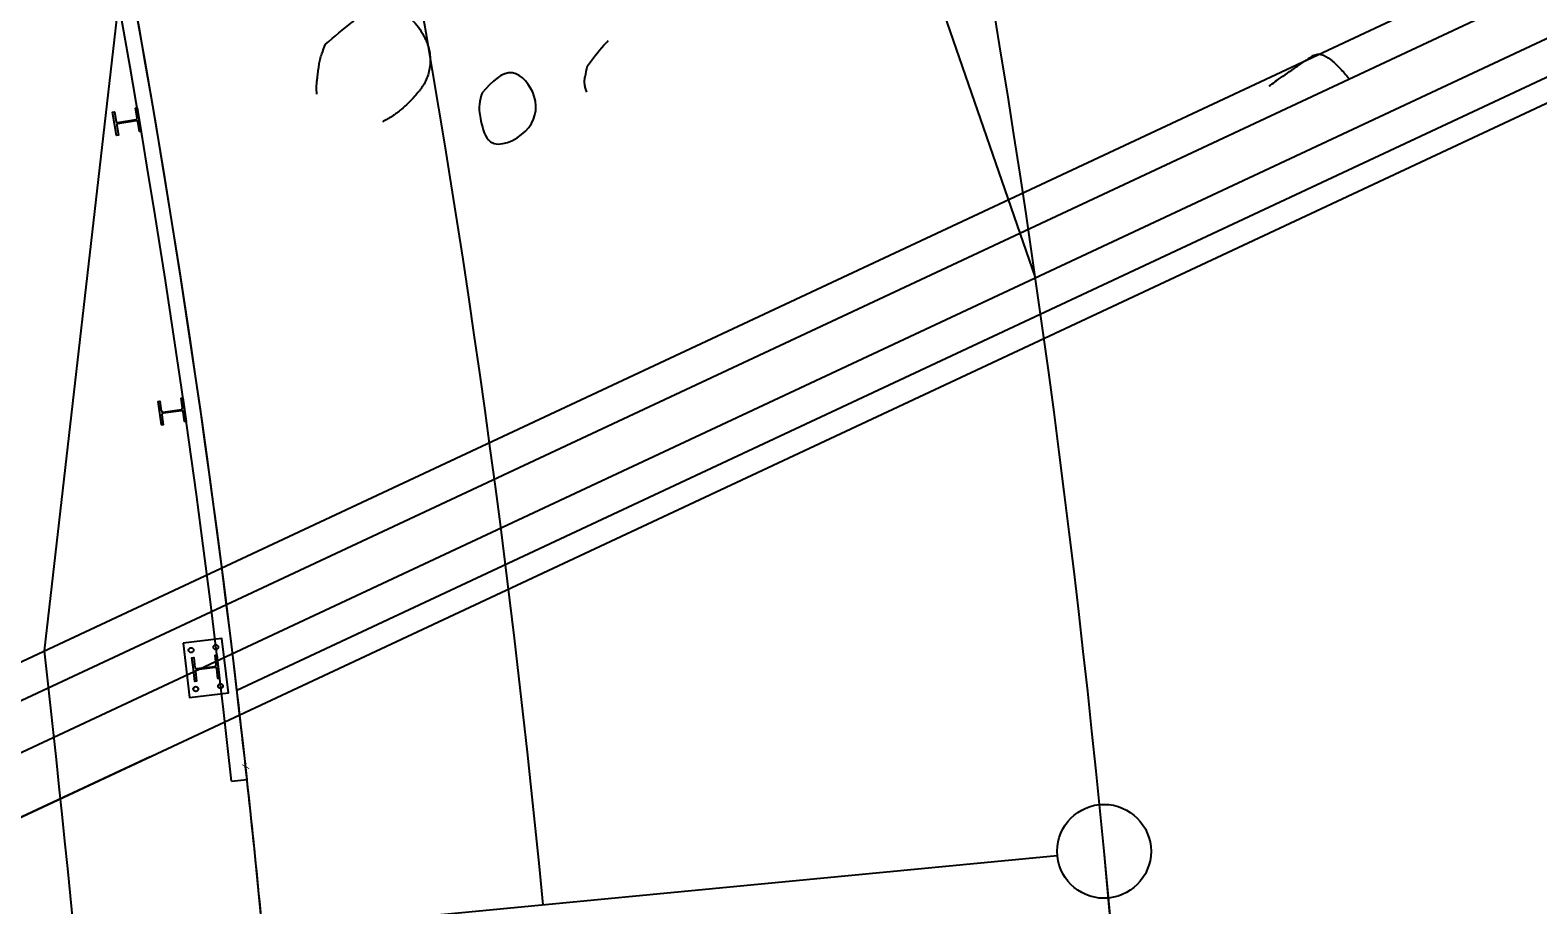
# Model space of a CAD drawing. Extents: x 2355002 to 2355569, y 708374 to 709566.
# Drawn here: x 2355338.73 to 2355370.84, y 709251.3 to 709269.92 of the extents above; entities that cross this region are included whole.
import ezdxf

# ---------------------------------------------------------------- set-up
doc = ezdxf.new("R2010")
doc.units = 0
for name, color, linetype in [('BD_X_Building', 7, 'Continuous'), ('BR_X_Brg_Centerline', 7, 'Continuous'), ('BR_X_Det_Centerline', 7, 'Continuous'), ('BR_X_Gen_Approach_Slab', 7, 'Continuous'), ('BR_X_Rail_Stl_Det', 7, 'Continuous'), ('BR_X_Slab_Object', 7, 'Continuous'), ('DR_X_Cells', 7, 'Continuous'), ('DT_X_Slope_Break_Line', 7, 'Continuous'), ('GK_Drainage_Nodes', 7, 'Continuous'), ('PM_X_CL_Double_Solid', 7, 'Continuous'), ('PM_X_Edge_Line', 7, 'Continuous'), ('PM_X_Stop_Line', 7, 'Continuous'), ('RD_X_GR_Rt', 7, 'Continuous'), ('RD_X_Wall', 7, 'Continuous'), ('SH_Text', 7, 'Continuous'), ('UT_X_Water_Cells', 7, 'Continuous'), ('VG_X_Cells', 7, 'Continuous'), ('VG_X_Tree_Line_Rt', 7, 'Continuous')]:
    doc.layers.add(name, color=color, linetype=linetype)

msp = doc.modelspace()

# ---------------------------------------------------------------- linework, layer by layer
at = {"layer": 'BD_X_Building'}
msp.add_arc((2355104.75, 709227.886), 272.024, 5.4603, 29.69206, dxfattribs=at)
at = {"layer": 'BR_X_Brg_Centerline'}
msp.add_line((2355335.913, 709253.31), (2355387.539, 709277.472), dxfattribs=at)
at = {"layer": 'BR_X_Det_Centerline'}
msp.add_line((2355360.141, 709264.65), (2355328.268, 709356.793), dxfattribs=at)
at = {"layer": 'BR_X_Gen_Approach_Slab'}
msp.add_line((2355343.137, 709255.863), (2355377.253, 709271.831), dxfattribs=at)
at = {"layer": 'BR_X_Rail_Stl_Det'}
msp.add_line((2355343.022, 709253.925), (2355343.353, 709253.961), dxfattribs=at)
for points in [[(2355340.533, 709267.925), (2355340.491, 709268.174), (2355340.528, 709268.181), (2355340.563, 709267.974)], [(2355340.598, 709267.949), (2355340.988, 709268.015)], [(2355340.993, 709267.989), (2355340.602, 709267.923)], [(2355341.013, 709268.05), (2355340.978, 709268.257), (2355341.015, 709268.263), (2355341.1, 709267.764), (2355341.062, 709267.758), (2355341.027, 709267.965)], [(2355340.578, 709267.888), (2355340.613, 709267.681), (2355340.576, 709267.675), (2355340.533, 709267.925)], [(2355341.497, 709261.764), (2355341.461, 709262.014), (2355341.499, 709262.02), (2355341.528, 709261.812)], [(2355341.98, 709261.876), (2355341.95, 709262.084), (2355341.987, 709262.09), (2355342.059, 709261.588), (2355342.022, 709261.583), (2355341.992, 709261.791)], [(2355341.541, 709261.726), (2355341.57, 709261.518), (2355341.533, 709261.513), (2355341.497, 709261.764)], [(2355341.562, 709261.786), (2355341.954, 709261.843)], [(2355341.958, 709261.816), (2355341.566, 709261.76)], [(2355341.992, 709256.865), (2355342.131, 709255.707), (2355342.958, 709255.806), (2355342.819, 709256.964), (2355341.992, 709256.865)], [(2355342.211, 709256.304), (2355342.181, 709256.555), (2355342.219, 709256.56), (2355342.244, 709256.351)], [(2355342.696, 709256.405), (2355342.671, 709256.614), (2355342.709, 709256.619), (2355342.769, 709256.116), (2355342.732, 709256.111), (2355342.707, 709256.32)], [(2355342.254, 709256.265), (2355342.279, 709256.057), (2355342.241, 709256.052), (2355342.211, 709256.304)], [(2355342.277, 709256.325), (2355342.67, 709256.372)], [(2355342.673, 709256.346), (2355342.28, 709256.299)]]:
    msp.add_lwpolyline(points, dxfattribs=at)
for centre in [(2355342.162, 709256.717), (2355342.689, 709256.781), (2355342.261, 709255.89), (2355342.789, 709255.953)]:
    msp.add_circle(centre, 0.0521, dxfattribs=at)
for centre, radius, start, end in [((2355104.75, 709227.887), 240.024, 6.23645, 29.69194), ((2355104.75, 709227.887), 239.69, 6.23645, 29.69194), ((2355340.593, 709267.979), 0.0298, 189.6373, 279.6373), ((2355340.983, 709268.045), 0.0298, 279.6373, 9.6373), ((2355340.998, 709267.96), 0.0298, 9.6373, 99.6373), ((2355340.607, 709267.893), 0.0298, 99.6373, 189.6373), ((2355341.95, 709261.872), 0.0298, 278.1433, 8.1433), ((2355341.558, 709261.816), 0.0298, 188.1433, 278.1433), ((2355341.57, 709261.731), 0.0298, 98.1433, 188.1433), ((2355341.962, 709261.787), 0.0298, 8.1433, 98.1433), ((2355342.273, 709256.355), 0.0298, 186.8504, 276.8504), ((2355342.284, 709256.269), 0.0298, 96.8504, 186.8504), ((2355342.667, 709256.402), 0.0298, 276.8504, 6.8504), ((2355342.677, 709256.316), 0.0298, 6.8504, 96.8504)]:
    msp.add_arc(centre, radius, start, end, dxfattribs=at)
at = {"layer": 'BR_X_Slab_Object'}
msp.add_arc((2355104.75, 709227.887), 240.024, 6.69347, 29.69206, dxfattribs=at)
at = {"layer": 'DR_X_Cells'}
for p, q in [((2355335.489, 709254.216), (2355342.916, 709257.692)), ((2355336.443, 709252.178), (2355343.198, 709255.34))]:
    msp.add_line(p, q, dxfattribs=at)
at = {"layer": 'DT_X_Slope_Break_Line'}
msp.add_line((2355341.287, 709254.445), (2355334.81, 709251.414), dxfattribs=at)
at = {"layer": 'GK_Drainage_Nodes'}
msp.add_line((2355335.171, 709254.895), (2355386.797, 709279.057), dxfattribs=at)
at = {"layer": 'PM_X_CL_Double_Solid'}
for centre, radius, start, end in [((2355104.75, 709227.886), 258.024, 5.4603, 29.69206), ((2355104.75, 709227.886), 258.024, 5.4603, 29.69206), ((2354973.054, 709215.293), 390.321, 334.29997, 5.46089), ((2354973.054, 709215.293), 390.321, 353.53196, 5.46089)]:
    msp.add_arc(centre, radius, start, end, dxfattribs=at)
at = {"layer": 'PM_X_Edge_Line'}
for radius in [270.024, 246.024]:
    msp.add_arc((2355104.75, 709227.886), radius, 5.4603, 29.69206, dxfattribs=at)
at = {"layer": 'PM_X_Stop_Line'}
for points in [[(2355345.025, 709269.62), (2355345.591, 709270.091), (2355345.645, 709270.132), (2355345.702, 709270.171), (2355345.826, 709270.241), (2355346.1, 709270.338), (2355346.382, 709270.362), (2355346.518, 709270.341), (2355346.583, 709270.32), (2355346.615, 709270.308), (2355346.646, 709270.294), (2355346.737, 709270.241), (2355346.822, 709270.177), (2355346.97, 709270.023), (2355347.09, 709269.845), (2355347.14, 709269.751), (2355347.162, 709269.704), (2355347.182, 709269.656), (2355347.204, 709269.594), (2355347.223, 709269.531), (2355347.248, 709269.402), (2355347.246, 709269.135), (2355347.17, 709268.868), (2355347.103, 709268.74), (2355347.061, 709268.678), (2355347.039, 709268.647), (2355347.015, 709268.617), (2355346.923, 709268.51), (2355346.638, 709268.231), (2355346.439, 709268.083), (2355346.338, 709268.021), (2355346.236, 709267.968)], [(2355344.841, 709268.552), (2355344.833, 709268.651), (2355344.835, 709268.749), (2355344.845, 709268.847), (2355344.857, 709268.945), (2355344.871, 709269.062), (2355344.887, 709269.18), (2355344.91, 709269.297), (2355344.945, 709269.411), (2355345.025, 709269.62)], [(2355350.605, 709269.16), (2355350.952, 709269.598), (2355351.046, 709269.697)], [(2355365.269, 709268.839), (2355365.648, 709269.101), (2355365.838, 709269.232), (2355365.933, 709269.296), (2355366.028, 709269.361), (2355366.052, 709269.376), (2355366.076, 709269.387), (2355366.124, 709269.402), (2355366.222, 709269.4), (2355366.423, 709269.297), (2355366.624, 709269.108), (2355366.723, 709269), (2355366.819, 709268.892), (2355366.828, 709268.883)], [(2355348.359, 709268.587), (2355349.003, 709269.012), (2355349.47, 709268.505), (2355349.285, 709267.769), (2355348.536, 709267.544), (2355348.333, 709267.991), (2355348.3, 709268.337), (2355348.359, 709268.587)], [(2355350.587, 709268.601), (2355350.571, 709268.641), (2355350.559, 709268.681), (2355350.544, 709268.762), (2355350.545, 709268.882), (2355350.552, 709268.922), (2355350.605, 709269.16)], [(2355365.122, 709268.726), (2355365.149, 709268.747), (2355365.283, 709268.849)]]:
    msp.add_spline(points, degree=3, dxfattribs=at)
at = {"layer": 'RD_X_GR_Rt'}
msp.add_arc((2355104.75, 709227.886), 240.024, 5.4603, 6.30212, dxfattribs=at)
at = {"layer": 'RD_X_Wall'}
msp.add_circle((2355361.603, 709252.435), 1, dxfattribs=at)
for centre, radius, start, end in [((2355104.75, 709227.886), 258.024, 5.4603, 29.69206), ((2354973.054, 709215.293), 390.321, 334.29997, 5.46089)]:
    msp.add_arc(centre, radius, start, end, dxfattribs=at)
at = {"layer": 'SH_Text'}
msp.add_line((2355360.608, 709252.34), (2355288.411, 709245.438), dxfattribs=at)
at = {"layer": 'UT_X_Water_Cells'}
msp.add_arc((2355104.75, 709227.887), 240.024, 5.4603, 6.69347, dxfattribs=at)
at = {"layer": 'VG_X_Cells'}
for p, q in [((2355342.916, 709257.692), (2355376.958, 709273.624)), ((2355343.198, 709255.34), (2355377.336, 709271.317))]:
    msp.add_line(p, q, dxfattribs=at)
at = {"layer": 'VG_X_Tree_Line_Rt'}
msp.add_line((2355339.039, 709256.705), (2355340.751, 709271.642), dxfattribs=at)
msp.add_arc((2354973.054, 709215.294), 368.32, 0.65261, 6.45558, dxfattribs=at)

# ---------------------------------------------------------------- texts
at = {"layer": 'BD_X_Building'}
msp.add_text('X', height=0.14, rotation=25.0808, dxfattribs=at).set_placement((2355343.298, 709254.145))

doc.saveas('drawing.dxf')
